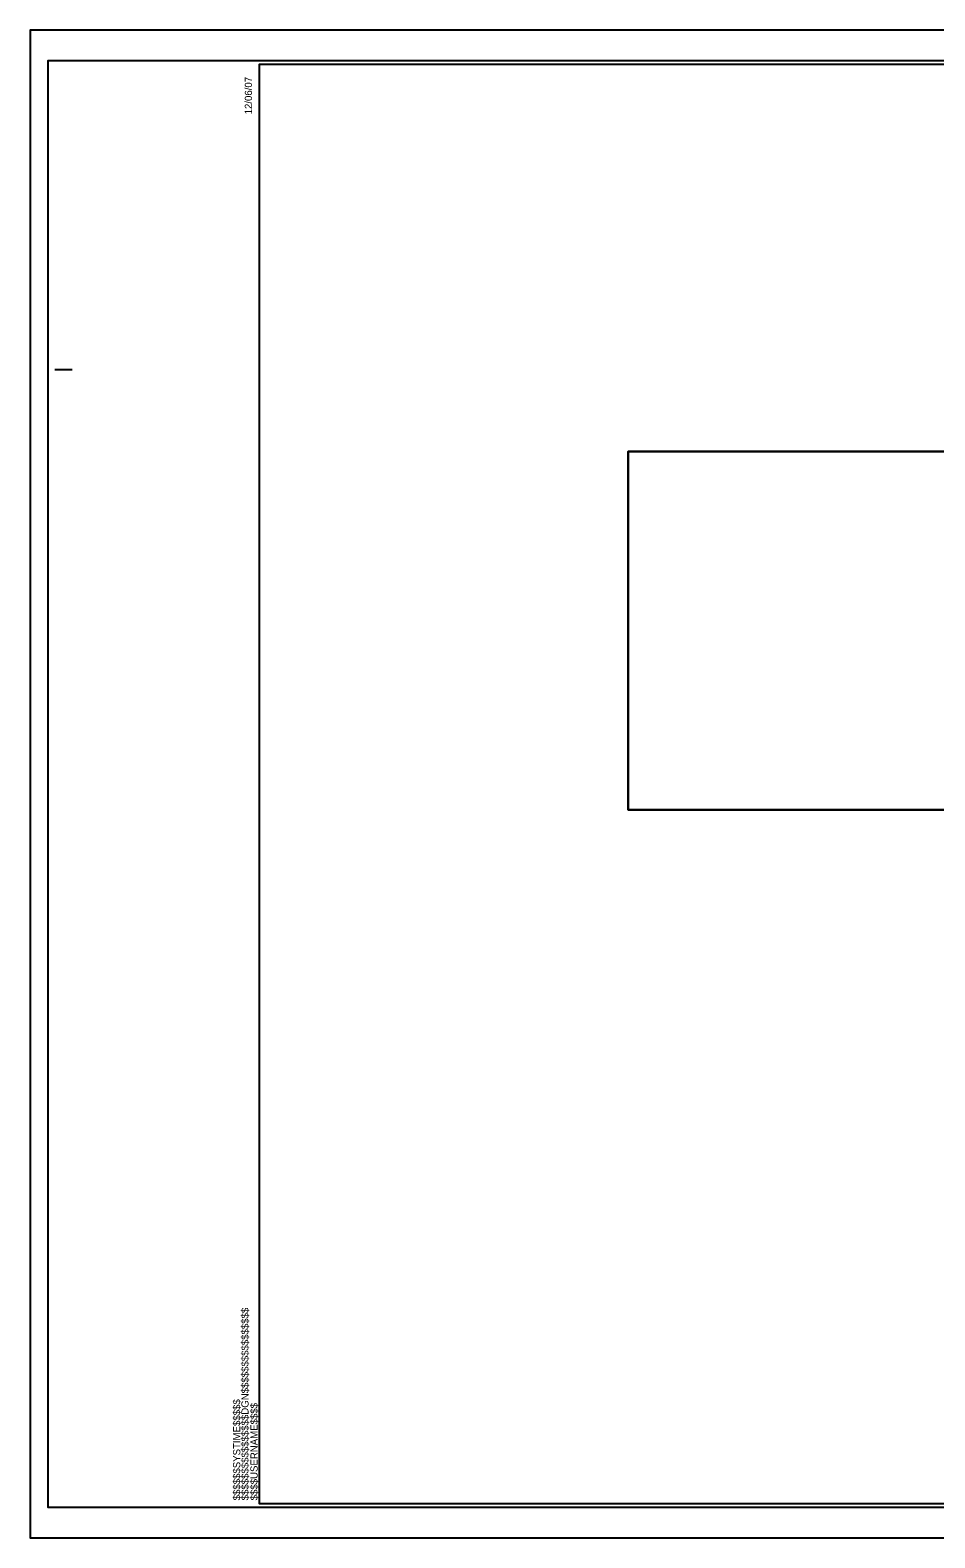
# Model space of a CAD drawing. Extents: x 1298931 to 1298964.7, y 1260171.5 to 1260193.5.
# Drawn here: x 1298930.99 to 1298944.19, y 1260171.47 to 1260193.47 of the extents above; entities that cross this region are included whole.
import ezdxf

# ---------------------------------------------------------------- set-up
doc = ezdxf.new("R2010")
doc.units = 0
for name, color, linetype in [('Default', 7, 'Continuous'), ('Sheet Cutting Line CELL', 7, 'Continuous'), ('Sheet Plot Border Inside CELL', 7, 'Continuous'), ('Sheet Plot Border Outside CELL', 7, 'Continuous'), ('Sheet Summary Combination CELL', 7, 'Continuous')]:
    doc.layers.add(name, color=color, linetype=linetype)

msp = doc.modelspace()

# ---------------------------------------------------------------- linework, layer by layer
at = {"layer": 'Default'}
for points in [[(1298939.715, 1260187.325), (1298958.847, 1260187.325), (1298958.847, 1260182.099), (1298939.715, 1260182.099)], [(1298939.715, 1260182.099), (1298958.847, 1260182.099), (1298958.847, 1260187.325), (1298939.715, 1260187.325)]]:
    msp.add_lwpolyline(points, close=True, dxfattribs=at)
at = {"layer": 'Sheet Cutting Line CELL'}
for p, q in [((1298964.671, 1260193.475), (1298930.991, 1260193.475)), ((1298930.991, 1260193.475), (1298930.991, 1260171.475)), ((1298930.991, 1260171.475), (1298964.671, 1260171.475))]:
    msp.add_line(p, q, dxfattribs=at)
at = {"layer": 'Sheet Plot Border Inside CELL'}
msp.add_lwpolyline([(1298964.581, 1260193.026), (1298931.251, 1260193.026), (1298931.251, 1260171.924), (1298964.581, 1260171.924)], close=True, dxfattribs=at)
at = {"layer": 'Sheet Plot Border Outside CELL'}
msp.add_lwpolyline([(1298964.671, 1260193.475), (1298930.991, 1260193.475), (1298930.991, 1260171.475), (1298964.671, 1260171.475)], close=True, dxfattribs=at)
at = {"layer": 'Sheet Summary Combination CELL'}
for p, q in [((1298931.353, 1260188.525), (1298931.603, 1260188.525)), ((1298934.331, 1260171.975), (1298934.331, 1260171.975))]:
    msp.add_line(p, q, dxfattribs=at)
msp.add_lwpolyline([(1298964.331, 1260192.975), (1298934.331, 1260192.975), (1298934.331, 1260171.975), (1298964.331, 1260171.975)], close=True, dxfattribs=at)

# ---------------------------------------------------------------- texts
for s, p in [('12/06/07', (1298934.228, 1260192.246)), ('$$$$$$$$$$$$$$$$DGN$$$$$$$$$$$$$$$$', (1298934.178, 1260172.022)), ('$$$$$$SYSTIME$$$$$', (1298934.057, 1260172.022)), ('$$$$USERNAME$$$$', (1298934.31, 1260172.022))]:
    msp.add_text(s, height=0.105, rotation=90, dxfattribs=at).set_placement(p)

doc.saveas('drawing.dxf')
